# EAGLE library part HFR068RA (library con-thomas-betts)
THOMAS&BETTS
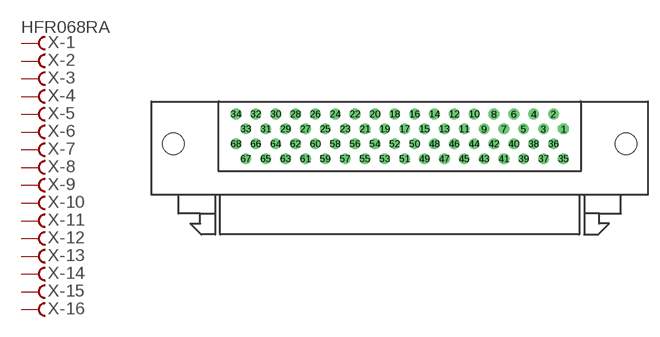
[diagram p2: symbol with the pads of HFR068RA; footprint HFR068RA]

Designator prefix X; gates -1=FV -2=F -3=F -4=F -5=F -6=F -7=F -8=F -9=F -10=F -11=F -12=F -13=F -14=F -15=F -16=F -17=F -18=F -19=F -20=F -21=F -22=F -23=F -24=F -25=F -26=F -27=F -28=F -29=F -30=F -31=F -32=F -33=F -34=F -36=F -37=F -38=F -39=F -40=F -41=F -42=F -43=F -44=F -45=F -46=F -47=F -48=F -49=F -50=F -51=F -52=F -53=F -54=F -55=F -56=F -57=F -58=F -59=F -60=F -61=F -62=F -63=F -64=F -65=F -66=F -67=F -68=F -35=F

## HFR068RA (OC_FARNELL: unknown; OC_NEWARK: unknown)  [HFR068RA]
1  -1:F  pas
2  -2:F  pas
3  -3:F  pas
4  -4:F  pas
5  -5:F  pas
6  -6:F  pas
7  -7:F  pas
8  -8:F  pas
9  -9:F  pas
10  -10:F  pas
11  -11:F  pas
12  -12:F  pas
13  -13:F  pas
14  -14:F  pas
15  -15:F  pas
16  -16:F  pas
17  -17:F  pas
18  -18:F  pas
19  -19:F  pas
20  -20:F  pas
21  -21:F  pas
22  -22:F  pas
23  -23:F  pas
24  -24:F  pas
25  -25:F  pas
26  -26:F  pas
27  -27:F  pas
28  -28:F  pas
29  -29:F  pas
30  -30:F  pas
31  -31:F  pas
32  -32:F  pas
33  -33:F  pas
34  -34:F  pas
35  -35:F  pas
36  -36:F  pas
37  -37:F  pas
38  -38:F  pas
39  -39:F  pas
40  -40:F  pas
41  -41:F  pas
42  -42:F  pas
43  -43:F  pas
44  -44:F  pas
45  -45:F  pas
46  -46:F  pas
47  -47:F  pas
48  -48:F  pas
49  -49:F  pas
50  -50:F  pas
51  -51:F  pas
52  -52:F  pas
53  -53:F  pas
54  -54:F  pas
55  -55:F  pas
56  -56:F  pas
57  -57:F  pas
58  -58:F  pas
59  -59:F  pas
60  -60:F  pas
61  -61:F  pas
62  -62:F  pas
63  -63:F  pas
64  -64:F  pas
65  -65:F  pas
66  -66:F  pas
67  -67:F  pas
68  -68:F  pas

## Footprint HFR068RA (pad centres in mm)
THOMAS&BETTS Fine Pitch "D" Connector HFR068RA29xxx
drill 0.864 octagon: 1 20.955,6.98
drill 0.864 round: 2 19.685,8.89; 3 18.415,6.98; 4 17.145,8.89; 5 15.875,6.98; 6 14.605,8.89; 7 13.335,6.98; 8 12.065,8.89; 9 10.795,6.98; 10 9.525,8.89; 11 8.255,6.98; 12 6.985,8.89; 13 5.715,6.98; 14 4.445,8.89; 15 3.175,6.98; 16 1.905,8.89; 17 0.635,6.98; 18 -0.635,8.89; 19 -1.905,6.98; 20 -3.175,8.89; 21 -4.445,6.98; 22 -5.715,8.89; 23 -6.985,6.98; 24 -8.255,8.89; 25 -9.525,6.98; 26 -10.795,8.89; 27 -12.065,6.98; 28 -13.335,8.89; 29 -14.605,6.98; 30 -15.875,8.89; 31 -17.145,6.98; 32 -18.415,8.89; 33 -19.685,6.98; 34 -20.955,8.89; 35 20.955,3.16; 36 19.685,5.07; 37 18.415,3.16; 38 17.145,5.07; 39 15.875,3.16; 40 14.605,5.07; 41 13.335,3.16; 42 12.065,5.07; 43 10.795,3.16; 44 9.525,5.07; 45 8.255,3.16; 46 6.985,5.07; 47 5.715,3.16; 48 4.445,5.07; 49 3.175,3.16; 50 1.905,5.07; 51 0.635,3.16; 52 -0.635,5.07; 53 -1.905,3.16; 54 -3.175,5.07; 55 -4.445,3.16; 56 -5.715,5.07; 57 -6.985,3.16; 58 -8.255,5.07; 59 -9.525,3.16; 60 -10.795,5.07; 61 -12.065,3.16; 62 -13.335,5.07; 63 -14.605,3.16; 64 -15.875,5.07; 65 -17.145,3.16; 66 -18.415,5.07; 67 -19.685,3.16; 68 -20.955,5.07
hole 2.769 at 28.956,5.07
hole 2.769 at -28.956,5.07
